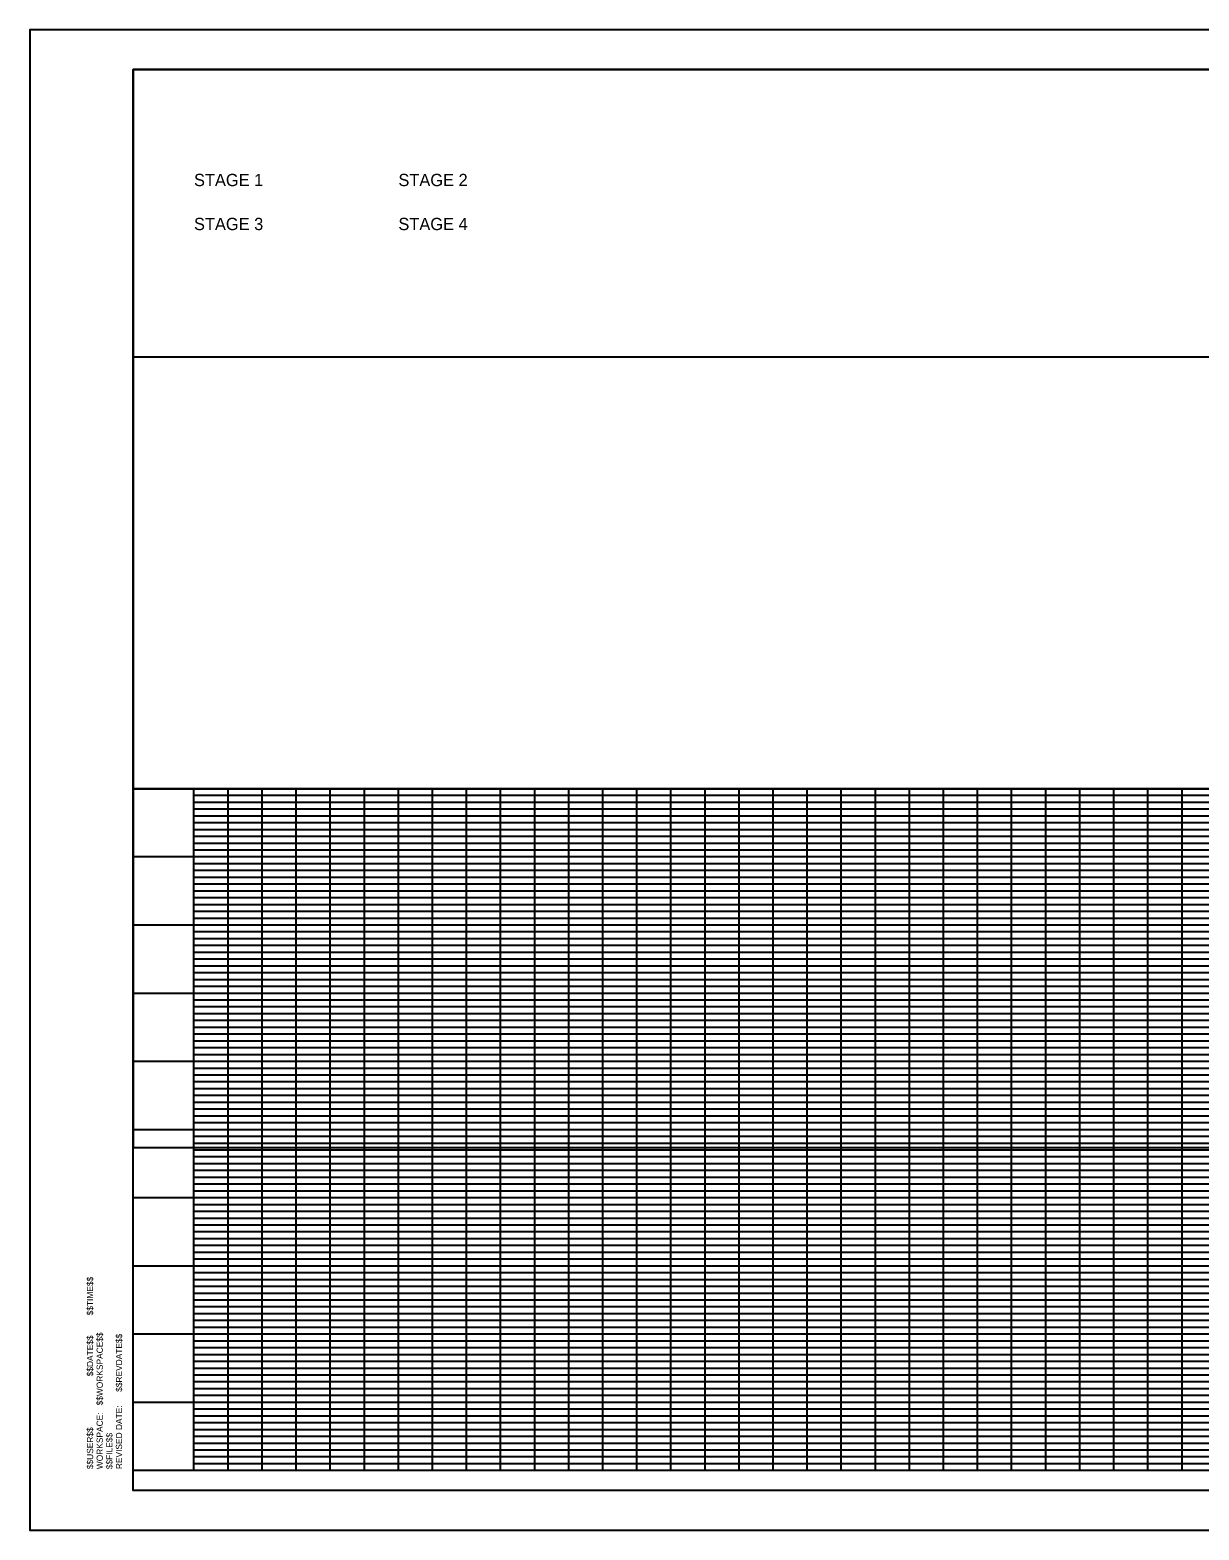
# Model space of a CAD drawing. Extents: x 0 to 1228740, y 0 to 152440.
# Drawn here: x 0 to 17.16, y 0 to 22 of the extents above; entities that cross this region are included whole.
import ezdxf

# ---------------------------------------------------------------- set-up
doc = ezdxf.new("R2010")
doc.units = 0
for name, color, linetype in [('G-TBLK', 7, 'Continuous'), ('R_Border', 7, 'Continuous'), ('R_Grid', 7, 'Continuous'), ('R_No Plot', 7, 'Continuous'), ('R_XS_EARTHWORK_STAGE1', 7, 'Continuous'), ('R_XS_EARTHWORK_STAGE2', 7, 'Continuous'), ('R_XS_EARTHWORK_STAGE3', 7, 'Continuous'), ('R_XS_EARTHWORK_STAGE4', 7, 'Continuous')]:
    doc.layers.add(name, color=color, linetype=linetype)

msp = doc.modelspace()

# ---------------------------------------------------------------- linework, layer by layer
at = {"layer": 'R_Border'}
for p, q in [((1.516, 21.423), (33.423, 21.423)), ((1.516, 0.577), (1.516, 21.423)), ((33.423, 0.577), (1.516, 0.577))]:
    msp.add_line(p, q, dxfattribs=at)
msp.add_lwpolyline([(34, 22), (0, 22), (0, 0), (34, 0)], close=True, dxfattribs=at)
at = {"layer": 'R_Grid'}
for p, q in [((33.423, 10.871), (1.516, 10.871)), ((2.407, 0.871), (2.407, 10.871)), ((2.907, 0.871), (2.907, 10.871)), ((3.407, 0.871), (3.407, 10.871)), ((3.907, 0.871), (3.907, 10.871)), ((4.407, 0.871), (4.407, 10.871)), ((4.907, 0.871), (4.907, 10.871)), ((5.407, 0.871), (5.407, 10.871)), ((5.907, 0.871), (5.907, 10.871)), ((6.407, 0.871), (6.407, 10.871)), ((6.907, 0.871), (6.907, 10.871)), ((7.407, 0.871), (7.407, 10.871)), ((7.907, 0.871), (7.907, 10.871)), ((8.407, 0.871), (8.407, 10.871)), ((8.907, 0.871), (8.907, 10.871)), ((9.407, 0.871), (9.407, 10.871)), ((9.907, 0.871), (9.907, 10.871)), ((10.407, 0.871), (10.407, 10.871)), ((10.907, 0.871), (10.907, 10.871)), ((11.407, 0.871), (11.407, 10.871)), ((11.907, 0.871), (11.907, 10.871)), ((12.407, 0.871), (12.407, 10.871)), ((12.907, 0.871), (12.907, 10.871)), ((13.407, 0.871), (13.407, 10.871)), ((13.907, 0.871), (13.907, 10.871)), ((14.407, 0.871), (14.407, 10.871)), ((14.907, 0.871), (14.907, 10.871)), ((15.407, 0.871), (15.407, 10.871)), ((15.907, 0.871), (15.907, 10.871)), ((16.407, 0.871), (16.407, 10.871)), ((16.907, 0.871), (16.907, 10.871)), ((32.407, 10.771), (2.407, 10.771)), ((32.407, 10.671), (2.407, 10.671)), ((32.407, 10.571), (2.407, 10.571)), ((32.407, 10.471), (2.407, 10.471)), ((32.407, 10.371), (2.407, 10.371)), ((32.407, 10.271), (2.407, 10.271)), ((32.407, 10.171), (2.407, 10.171)), ((32.407, 10.071), (2.407, 10.071)), ((32.407, 9.971), (2.407, 9.971)), ((33.423, 9.871), (1.516, 9.871)), ((32.407, 9.771), (2.407, 9.771)), ((32.407, 9.671), (2.407, 9.671)), ((32.407, 9.571), (2.407, 9.571)), ((32.407, 9.471), (2.407, 9.471)), ((32.407, 9.371), (2.407, 9.371)), ((32.407, 9.271), (2.407, 9.271)), ((32.407, 9.171), (2.407, 9.171)), ((32.407, 9.071), (2.407, 9.071)), ((33.423, 8.871), (1.516, 8.871)), ((32.407, 8.971), (2.407, 8.971)), ((32.407, 8.771), (2.407, 8.771)), ((32.407, 8.671), (2.407, 8.671)), ((32.407, 8.571), (2.407, 8.571)), ((32.407, 8.471), (2.407, 8.471)), ((32.407, 8.371), (2.407, 8.371)), ((32.407, 8.271), (2.407, 8.271)), ((32.407, 8.171), (2.407, 8.171)), ((32.407, 8.071), (2.407, 8.071)), ((32.407, 7.971), (2.407, 7.971)), ((33.423, 7.871), (1.516, 7.871)), ((32.407, 7.771), (2.407, 7.771)), ((32.407, 7.671), (2.407, 7.671)), ((32.407, 7.571), (2.407, 7.571)), ((32.407, 7.471), (2.407, 7.471)), ((32.407, 7.371), (2.407, 7.371)), ((32.407, 7.271), (2.407, 7.271)), ((32.407, 7.171), (2.407, 7.171)), ((32.407, 7.071), (2.407, 7.071)), ((33.423, 6.871), (1.516, 6.871)), ((32.407, 6.971), (2.407, 6.971)), ((32.407, 6.771), (2.407, 6.771)), ((32.407, 6.671), (2.407, 6.671)), ((32.407, 6.571), (2.407, 6.571)), ((32.407, 6.471), (2.407, 6.471)), ((32.407, 6.371), (2.407, 6.371)), ((32.407, 6.271), (2.407, 6.271)), ((32.407, 6.171), (2.407, 6.171)), ((32.407, 6.071), (2.407, 6.071)), ((32.407, 5.971), (2.407, 5.971)), ((33.423, 5.871), (1.516, 5.871)), ((32.407, 5.771), (2.407, 5.771)), ((32.407, 5.671), (2.407, 5.671)), ((32.407, 5.571), (2.407, 5.571)), ((32.407, 5.471), (2.407, 5.471)), ((32.407, 5.371), (2.407, 5.371)), ((32.407, 5.271), (2.407, 5.271)), ((32.407, 5.171), (2.407, 5.171)), ((32.407, 5.071), (2.407, 5.071)), ((33.423, 4.871), (1.516, 4.871)), ((32.407, 4.971), (2.407, 4.971)), ((32.407, 4.771), (2.407, 4.771)), ((32.407, 4.671), (2.407, 4.671)), ((32.407, 4.571), (2.407, 4.571)), ((32.407, 4.471), (2.407, 4.471)), ((32.407, 4.371), (2.407, 4.371)), ((32.407, 4.271), (2.407, 4.271)), ((32.407, 4.171), (2.407, 4.171)), ((32.407, 4.071), (2.407, 4.071)), ((32.407, 3.971), (2.407, 3.971)), ((33.423, 3.871), (1.516, 3.871)), ((32.407, 3.771), (2.407, 3.771)), ((32.407, 3.671), (2.407, 3.671)), ((32.407, 3.571), (2.407, 3.571)), ((32.407, 3.471), (2.407, 3.471)), ((32.407, 3.371), (2.407, 3.371)), ((32.407, 3.271), (2.407, 3.271)), ((32.407, 3.171), (2.407, 3.171)), ((33.423, 2.871), (1.516, 2.871)), ((32.407, 3.071), (2.407, 3.071)), ((32.407, 2.971), (2.407, 2.971)), ((32.407, 2.771), (2.407, 2.771)), ((32.407, 2.671), (2.407, 2.671)), ((32.407, 2.571), (2.407, 2.571)), ((32.407, 2.471), (2.407, 2.471)), ((32.407, 2.371), (2.407, 2.371)), ((32.407, 2.271), (2.407, 2.271)), ((32.407, 2.171), (2.407, 2.171)), ((32.407, 2.071), (2.407, 2.071)), ((33.423, 1.871), (1.516, 1.871)), ((32.407, 1.971), (2.407, 1.971)), ((32.407, 1.771), (2.407, 1.771)), ((32.407, 1.671), (2.407, 1.671)), ((32.407, 1.571), (2.407, 1.571)), ((32.407, 1.471), (2.407, 1.471)), ((32.407, 1.371), (2.407, 1.371)), ((32.407, 1.271), (2.407, 1.271)), ((32.407, 1.171), (2.407, 1.171)), ((32.407, 1.071), (2.407, 1.071)), ((32.407, 0.971), (2.407, 0.971)), ((33.423, 0.871), (1.516, 0.871))]:
    msp.add_line(p, q, dxfattribs=at)
at = {"layer": 'R_No Plot'}
msp.add_lwpolyline([(33.423, 17.405), (33.423, 0.577), (1.516, 0.577), (1.516, 21.423), (20.267, 21.423), (20.267, 20.435), (28.757, 20.435), (28.757, 20.087), (29.113, 20.087), (29.113, 20.143), (30.667, 20.143)], dxfattribs=at)
for points in [[(20.267, 21.423), (1.516, 21.423), (1.516, 10.871), (33.423, 10.871), (33.423, 17.405), (30.667, 17.405), (30.667, 20.143), (29.113, 20.143), (29.113, 20.087), (28.757, 20.087), (28.757, 20.435), (20.267, 20.435)], [(33.423, 17.202), (1.516, 17.202), (1.516, 5.61), (33.423, 5.61)], [(1.516, 10.871), (33.423, 10.871), (33.423, 0.577), (1.516, 0.577)]]:
    msp.add_lwpolyline(points, close=True, dxfattribs=at)

# ---------------------------------------------------------------- texts
at = {"layer": 'G-TBLK'}
for s, p in [('$$TIME$$', (0.927, 3.148)), ('$$WORKSPACE$$', (1.069, 1.827)), ('$$REVDATE$$', (1.352, 2.026)), ('$$DATE$$', (0.927, 2.254)), ('REVISED DATE:', (1.352, 0.893)), ('WORKSPACE:', (1.069, 0.892)), ('$$USER$$', (0.927, 0.892)), ('$$FILE$$', (1.211, 0.892))]:
    msp.add_text(s, height=0.0918, rotation=90, dxfattribs=at).set_placement(p)
at = {"layer": 'R_XS_EARTHWORK_STAGE1'}
msp.add_text('STAGE 1', height=0.18, dxfattribs=at).set_placement((2.407, 19.71))
at = {"layer": 'R_XS_EARTHWORK_STAGE2'}
msp.add_text('STAGE 2', height=0.18, dxfattribs=at).set_placement((5.407, 19.71))
at = {"layer": 'R_XS_EARTHWORK_STAGE3'}
msp.add_text('STAGE 3', height=0.18, dxfattribs=at).set_placement((2.407, 19.065))
at = {"layer": 'R_XS_EARTHWORK_STAGE4'}
msp.add_text('STAGE 4', height=0.18, dxfattribs=at).set_placement((5.407, 19.065))

doc.saveas('drawing.dxf')
